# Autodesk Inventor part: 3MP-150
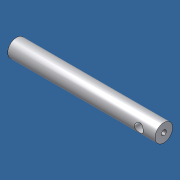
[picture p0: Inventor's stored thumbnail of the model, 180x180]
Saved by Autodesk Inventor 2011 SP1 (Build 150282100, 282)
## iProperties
Created: 2006-01
Part Number: 3MP-150
Document SubType Name: Modeling
Designer: Darius
Density: 1 g/cm^3
Author: Darius
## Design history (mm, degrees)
sketch "Sketch1"
  geometry: L1 (-77.672, 2.874)-(-77.672, 8.874); L2 (-77.672, 8.874)-(22.328, 8.874); L3 (22.328, 8.874)-(22.328, 2.874); L4 (22.328, 2.874)-(14.328, 2.874); L5 (8.328, 2.874)-(-77.672, 2.874); A1 r 3 centre (11.328, 2.874) between (14.328, 2.874) and (8.328, 2.874)
  constraints: 10 end point, 3 parallel, 2 point on circle, 1 centre point, 1 perpendicular, 1 point on line, 1 vertical
  dimensions: "d0" = 6 distance of L1.start L1.end; "d1" = 11 distance from line of L3 A1.centre; "d2" = 100 distance of L1.end L2.end; "d3" = 3 radius of A1; "d38" = 0 distance between parallel lines of L5 L4
revolve "Revolution1" sketch "Sketch1" stored, may be unused: angle "d4" = 90 deg
sketch "Sketch2"
  geometry: L1 (0, 0)-(0, 6); L2 (0, 0)-(-6, 0); A1 r 6 centre (0, 0) between (0, 6) and (-6, 0) reference
  constraints: 4 end point, 2 point on circle, 1 perpendicular, 1 vertical
workaxis "Work Axis1"
workplane "Work Plane1"
sketch "Sketch5"
  geometry: C1 r 6 at (0, 0) reference; 1 further point
  constraints: 1 coincident
hole "Hole3" sketch "Sketch5" at (0, 0) diameter "d24" = 3.459; stored, may be unused: countersink angle "d28" = 90 deg, drill point angle "d30" = 118 deg; dims "d25" = 6.5, "d26" = 4, "d27" = 2, "d29" = 11
sketch "Sketch6"
  geometry: C1 r 6 at (0, 0) reference; 1 further point
  constraints: 1 coincident
hole "Hole4" sketch "Sketch6" at (0, 0) diameter "d31" = 5.459; stored, may be unused: countersink angle "d35" = 90 deg, drill point angle "d37" = 118 deg; dims "d32" = 6.5, "d33" = 4, "d34" = 2, "d36" = 7.5
sketch "Sketch7"
  geometry: L1 (0, 0)-(-15.889, 0); C1 r 1.73 at (0, 0) reference; C2 r 6 at (0, 0) reference
  constraints: 2 end point, 1 horizontal
workaxis "Work Axis2"
workplane "Work Plane2"
workplane "Work Plane3"
sketch "Sketch8"
  geometry: L1 (-50, 6)-(-50, -6) reference; L2 (-50, 0)-(-71.056, 0); 1 further point
  constraints: 2 end point, 1 midpoint, 1 perpendicular
  dimensions: "d39" = 11 distance from line of point (-39, 0) L1; "d40" = 0 distance from line of L2 point (-39, 0)
hole "Hole5" sketch "Sketch8" at (-39, 0) diameter "d41" = 6; stored, may be unused: countersink angle "d45" = 90 deg, drill point angle "d47" = 118 deg; dims "d42" = 6, "d43" = 4, "d44" = 2, "d46" = 8
body "Solid1"
other parameters: "d5" = 90 deg
